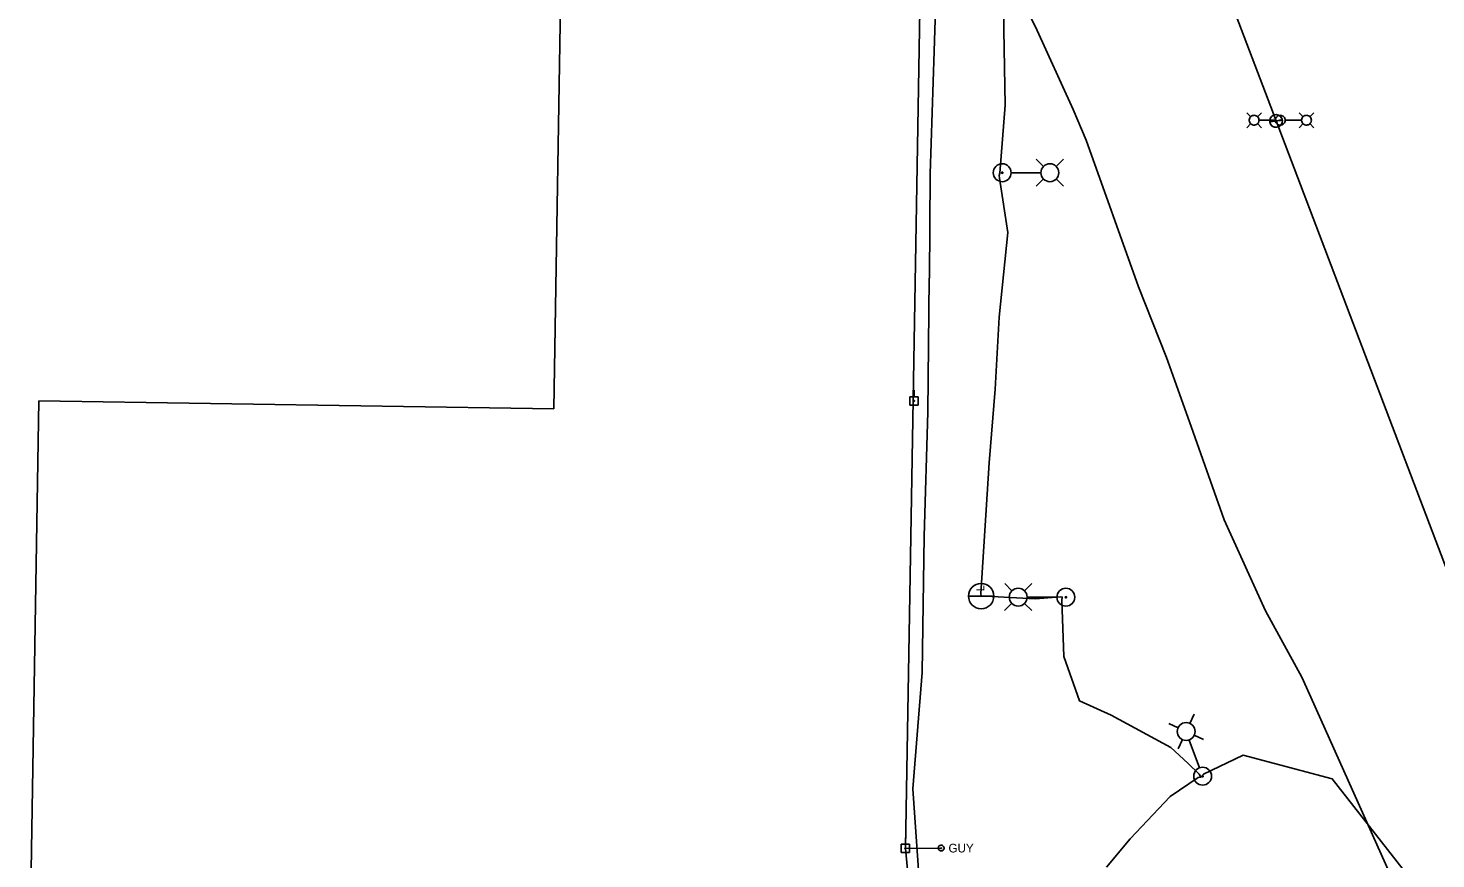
# Model space of a CAD drawing. Extents: x 596028 to 606371, y 330010 to 403088.
# Drawn here: x 603062 to 603685, y 350437 to 350805 of the extents above; entities that cross this region are included whole.
import ezdxf

# ---------------------------------------------------------------- set-up
doc = ezdxf.new("R2010")
doc.units = 0
for name, color, linetype in [('E_FTMS_Conduit', 7, 'Continuous'), ('E_LTG', 7, 'Continuous'), ('E_LTG_CID', 7, 'Continuous'), ('E_UTL_E_UG', 7, 'Continuous'), ('E_UTL_EGuyWire', 7, 'Continuous'), ('E_UTL_EPowerPole', 7, 'Continuous'), ('E_UTL_FO_UG_QWEST', 7, 'Continuous'), ('E_UTL_Overhead', 7, 'Continuous')]:
    doc.layers.add(name, color=color, linetype=linetype)

# ---------------------------------------------------------------- blocks, each defined once
blk = doc.blocks.new('_U288')
at = {"layer": 'E_LTG'}
blk.add_lwpolyline([(0.001, -0.171), (0.001, 0.172)], dxfattribs=at)
blk.add_circle((0.001, 0), 0.171, dxfattribs=at)
blk.add_arc((0.001, 0), 0.171, 90, 270, dxfattribs=at)
blk.add_text('L', height=0.108, dxfattribs=at).set_placement((0.066, -0.042))
blk = doc.blocks.new('_U272')
at = {"layer": 'E_LTG'}
blk.add_lwpolyline([(0.001, -0.171), (0.001, 0.172)], dxfattribs=at)
blk.add_circle((0.001, 0), 0.171, dxfattribs=at)
blk.add_arc((0.001, 0), 0.171, 90, 270, dxfattribs=at)
blk.add_text('L', height=0.108, dxfattribs=at).set_placement((0.066, -0.042))

msp = doc.modelspace()

# ---------------------------------------------------------------- linework, layer by layer
at = {"layer": 'E_FTMS_Conduit'}
msp.add_lwpolyline([(603683.28, 350388.39), (603627.38, 350513.3), (603625.35, 350517.8), (603609.26, 350547.29), (603590.93, 350587.57), (603576.33, 350628.92), (603565.39, 350659.37), (603552.92, 350690.81), (603529.87, 350755.72), (603524.01, 350769.33), (603507.4, 350805.93), (603488.24, 350844.06), (603483.2, 350870.26), (603473.58, 350908.61), (603465.8, 350950.07), (603458.47, 350983.69), (603437.61, 351034.41), (603419.58, 351080.05), (603403.21, 351158.05), (603376.31, 351235.86)], dxfattribs=at)
at = {"layer": 'E_LTG'}
for points in [[(603602.64, 350766.07), (603600.87, 350767.84)], [(603606.34, 350764.54), (603606.31, 350764.96), (603606.19, 350765.35), (603606, 350765.72), (603605.74, 350766.05), (603605.43, 350766.32), (603605.07, 350766.52), (603604.68, 350766.66), (603604.27, 350766.72), (603603.86, 350766.7), (603603.46, 350766.6), (603603.08, 350766.43), (603602.74, 350766.19), (603602.46, 350765.89), (603602.24, 350765.54), (603602.08, 350765.16), (603602, 350764.75), (603602, 350764.34), (603602.08, 350763.93), (603602.24, 350763.55), (603602.46, 350763.2), (603602.74, 350762.9), (603603.08, 350762.66), (603603.46, 350762.49), (603603.86, 350762.39), (603604.27, 350762.37), (603604.68, 350762.43), (603605.07, 350762.56), (603605.43, 350762.77), (603605.74, 350763.04), (603606, 350763.37), (603606.19, 350763.74), (603606.31, 350764.13), (603606.34, 350764.54)], [(603605.69, 350766.07), (603607.47, 350767.84)], [(603617.91, 350764.54), (603617.87, 350764.96), (603617.75, 350765.35), (603617.56, 350765.72), (603617.31, 350766.04), (603617, 350766.32), (603616.64, 350766.52), (603616.25, 350766.66), (603615.84, 350766.72), (603615.43, 350766.7), (603615.02, 350766.6), (603614.65, 350766.43), (603614.31, 350766.19), (603614.02, 350765.89), (603613.8, 350765.54), (603613.65, 350765.16), (603613.57, 350764.75), (603613.57, 350764.34), (603613.65, 350763.93), (603613.8, 350763.55), (603614.02, 350763.2), (603614.31, 350762.9), (603614.65, 350762.66), (603615.02, 350762.49), (603615.43, 350762.39), (603615.84, 350762.37), (603616.25, 350762.43), (603616.64, 350762.56), (603617, 350762.77), (603617.31, 350763.04), (603617.56, 350763.37), (603617.75, 350763.73), (603617.87, 350764.13), (603617.91, 350764.54)], [(603625.82, 350766.07), (603624.04, 350767.84)], [(603629.51, 350764.54), (603629.47, 350764.96), (603629.36, 350765.35), (603629.17, 350765.72), (603628.91, 350766.04), (603628.6, 350766.32), (603628.24, 350766.52), (603627.85, 350766.66), (603627.44, 350766.72), (603627.03, 350766.7), (603626.63, 350766.6), (603626.25, 350766.43), (603625.91, 350766.19), (603625.63, 350765.89), (603625.4, 350765.54), (603625.25, 350765.16), (603625.17, 350764.75), (603625.17, 350764.34), (603625.25, 350763.93), (603625.4, 350763.55), (603625.63, 350763.2), (603625.91, 350762.9), (603626.25, 350762.66), (603626.63, 350762.49), (603627.03, 350762.39), (603627.44, 350762.37), (603627.85, 350762.43), (603628.24, 350762.56), (603628.6, 350762.77), (603628.91, 350763.04), (603629.17, 350763.37), (603629.36, 350763.73), (603629.47, 350764.13), (603629.51, 350764.54)], [(603628.86, 350766.07), (603630.64, 350767.84)], [(603602.64, 350763.02), (603600.87, 350761.24)], [(603605.69, 350763.02), (603607.47, 350761.24)], [(603606.38, 350764.54), (603613.56, 350764.54)], [(603615.9, 350764.54), (603615.9, 350764.57), (603615.89, 350764.61), (603615.87, 350764.63), (603615.86, 350764.66), (603615.83, 350764.68), (603615.8, 350764.69), (603615.77, 350764.71), (603615.74, 350764.71), (603615.71, 350764.71), (603615.68, 350764.7), (603615.65, 350764.69), (603615.63, 350764.67), (603615.6, 350764.65), (603615.59, 350764.62), (603615.58, 350764.59), (603615.57, 350764.56), (603615.57, 350764.53), (603615.58, 350764.5), (603615.59, 350764.47), (603615.6, 350764.44), (603615.63, 350764.42), (603615.65, 350764.4), (603615.68, 350764.39), (603615.71, 350764.38), (603615.74, 350764.38), (603615.77, 350764.38), (603615.8, 350764.39), (603615.83, 350764.41), (603615.86, 350764.43), (603615.87, 350764.45), (603615.89, 350764.48), (603615.9, 350764.51), (603615.9, 350764.54)], [(603625.13, 350764.54), (603617.95, 350764.54)], [(603625.82, 350763.02), (603624.04, 350761.24)], [(603628.86, 350763.02), (603630.64, 350761.24)], [(603511, 350744.06), (603507.77, 350747.28)], [(603516.54, 350744.06), (603519.77, 350747.28)], [(603509.74, 350741.28), (603496.69, 350741.28)], [(603511, 350738.51), (603507.77, 350735.28)], [(603516.54, 350738.51), (603519.77, 350735.28)], [(603497, 350556.09), (603493.78, 350559.33)], [(603502.54, 350556.07), (603505.78, 350559.3)], [(603496.98, 350550.55), (603493.75, 350547.33)], [(603502.52, 350550.53), (603505.75, 350547.3)], [(603503.79, 350553.3), (603516.84, 350553.27)], [(603575.7, 350497.33), (603577.61, 350501.48)], [(603570.5, 350495.41), (603566.36, 350497.32)], [(603577.62, 350492.13), (603581.77, 350490.22)], [(603572.42, 350490.21), (603570.52, 350486.06)], [(603575.46, 350489.99), (603579.99, 350477.75)]]:
    msp.add_lwpolyline(points, dxfattribs=at)
for centre, radius in [((603492.67, 350741.28), 3.96), ((603492.67, 350741.28), 0.303), ((603513.77, 350741.28), 3.96), ((603499.76, 350553.31), 3.96), ((603520.86, 350553.26), 3.96), ((603520.86, 350553.26), 0.303), ((603574.07, 350493.77), 3.96), ((603581.38, 350473.98), 3.96), ((603581.38, 350473.98), 0.303)]:
    msp.add_circle(centre, radius, dxfattribs=at)
at = {"layer": 'E_LTG_CID'}
for points in [[(604318.05, 348339.7), (604287.36, 348606.91), (604242.16, 348872.6), (604188.57, 349120.13), (604125.01, 349362.84), (604050.82, 349602.08), (604014.23, 349708.06), (603966.43, 349837.54), (603869.82, 350091.09), (603838.85, 350172.22), (603784.41, 350315.72), (603699.29, 350539.43), (603613.87, 350764.2), (603510.34, 351036.54), (603442.84, 351213.06), (603357.76, 351436.96)], [(603580.58, 350473.53), (603579.82, 350474.91), (603574.76, 350479.76), (603567.26, 350486.74), (603540.84, 350501.01), (603526.89, 350507.31), (603519.96, 350527.04), (603519.11, 350552.01), (603519.26, 350553.28), (603518.57, 350553.45), (603507.25, 350552.53), (603488.13, 350553.6), (603484.67, 350553.73), (603483.36, 350553.72), (603483.27, 350554.85), (603484.6, 350575.79), (603486.87, 350612.75), (603489.62, 350645.46), (603491.33, 350677.37), (603495.09, 350714.78), (603491.49, 350738.84), (603491.38, 350740.03), (603491.57, 350741.16), (603494.03, 350771.18), (603493.35, 350804.53), (603492.94, 350842.91)], [(603613.87, 350764.2), (603615.73, 350764.54)], [(603538.88, 350433.66), (603549.37, 350446.22), (603567.07, 350464.96), (603579.39, 350473.35), (603580.58, 350473.53), (603581.78, 350474.86), (603599.32, 350483.29), (603638.74, 350472.78), (603670.13, 350432.71)]]:
    msp.add_lwpolyline(points, dxfattribs=at)
at = {"layer": 'E_UTL_E_UG'}
msp.add_line((603061.58, 350355.6), (603066.26, 350640.24), dxfattribs=at)
msp.add_lwpolyline([(603066.26, 350640.24), (603294.23, 350636.71), (603301.03, 351049.72)], dxfattribs=at)
at = {"layer": 'E_UTL_EGuyWire'}
msp.add_line((603465.68, 350442.13), (603449.86, 350441.98), dxfattribs=at)
for points in [[(603466.96, 350442.13), (603466.94, 350442.37), (603466.87, 350442.61), (603466.76, 350442.82), (603466.61, 350443.01), (603466.42, 350443.17), (603466.21, 350443.3), (603465.98, 350443.38), (603465.74, 350443.41), (603465.5, 350443.4), (603465.26, 350443.34), (603465.04, 350443.24), (603464.84, 350443.1), (603464.67, 350442.92), (603464.54, 350442.72), (603464.45, 350442.49), (603464.4, 350442.25), (603464.4, 350442.01), (603464.45, 350441.77), (603464.54, 350441.54), (603464.67, 350441.34), (603464.84, 350441.16), (603465.04, 350441.02), (603465.26, 350440.92), (603465.5, 350440.86), (603465.74, 350440.85), (603465.98, 350440.88), (603466.21, 350440.96), (603466.42, 350441.08), (603466.61, 350441.24), (603466.76, 350441.44), (603466.87, 350441.65), (603466.94, 350441.89), (603466.96, 350442.13)], [(603465.84, 350442.13), (603465.84, 350442.16), (603465.83, 350442.19), (603465.81, 350442.22), (603465.79, 350442.24), (603465.77, 350442.26), (603465.74, 350442.27), (603465.72, 350442.28), (603465.69, 350442.29), (603465.66, 350442.29), (603465.63, 350442.28), (603465.6, 350442.27), (603465.57, 350442.25), (603465.55, 350442.23), (603465.54, 350442.2), (603465.52, 350442.17), (603465.52, 350442.14), (603465.52, 350442.11), (603465.52, 350442.08), (603465.54, 350442.06), (603465.55, 350442.03), (603465.57, 350442.01), (603465.6, 350441.99), (603465.63, 350441.98), (603465.66, 350441.97), (603465.69, 350441.97), (603465.72, 350441.97), (603465.74, 350441.98), (603465.77, 350442), (603465.79, 350442.02), (603465.81, 350442.04), (603465.83, 350442.07), (603465.84, 350442.1), (603465.84, 350442.13)]]:
    msp.add_lwpolyline(points, dxfattribs=at)
at = {"layer": 'E_UTL_EPowerPole'}
for points in [[(603455.48, 350642.06), (603451.8, 350642.06)], [(603451.8, 350642.06), (603451.8, 350638.37)], [(603453.64, 350642.06), (603453.64, 350644.97)], [(603455.48, 350638.37), (603455.48, 350642.06)], [(603451.8, 350638.37), (603455.48, 350638.37)], [(603453.91, 350640.22), (603453.91, 350640.27), (603453.89, 350640.31), (603453.87, 350640.35), (603453.85, 350640.38), (603453.81, 350640.41), (603453.77, 350640.44), (603453.73, 350640.45), (603453.68, 350640.46), (603453.64, 350640.46), (603453.6, 350640.45), (603453.55, 350640.43), (603453.52, 350640.4), (603453.49, 350640.37), (603453.46, 350640.33), (603453.44, 350640.29), (603453.44, 350640.24), (603453.44, 350640.2), (603453.44, 350640.15), (603453.46, 350640.11), (603453.49, 350640.07), (603453.52, 350640.04), (603453.55, 350640.01), (603453.6, 350639.99), (603453.64, 350639.98), (603453.68, 350639.98), (603453.73, 350639.99), (603453.77, 350640), (603453.81, 350640.03), (603453.85, 350640.06), (603453.87, 350640.09), (603453.89, 350640.13), (603453.91, 350640.17), (603453.91, 350640.22)], [(603451.68, 350443.83), (603447.99, 350443.83)], [(603447.99, 350443.83), (603447.99, 350440.14)], [(603450.1, 350441.98), (603450.1, 350442.03), (603450.09, 350442.07), (603450.07, 350442.11), (603450.04, 350442.15), (603450, 350442.18), (603449.96, 350442.2), (603449.92, 350442.22), (603449.88, 350442.22), (603449.83, 350442.22), (603449.79, 350442.21), (603449.75, 350442.19), (603449.71, 350442.17), (603449.68, 350442.13), (603449.65, 350442.09), (603449.64, 350442.05), (603449.63, 350442.01), (603449.63, 350441.96), (603449.64, 350441.92), (603449.65, 350441.88), (603449.68, 350441.84), (603449.71, 350441.8), (603449.75, 350441.78), (603449.79, 350441.76), (603449.83, 350441.75), (603449.88, 350441.75), (603449.92, 350441.75), (603449.96, 350441.77), (603450, 350441.79), (603450.04, 350441.82), (603450.07, 350441.86), (603450.09, 350441.9), (603450.1, 350441.94), (603450.1, 350441.98)], [(603449.83, 350443.83), (603449.83, 350446.74)], [(603451.68, 350440.14), (603451.68, 350443.83)], [(603447.99, 350440.14), (603451.68, 350440.14)]]:
    msp.add_lwpolyline(points, dxfattribs=at)
at = {"layer": 'E_UTL_FO_UG_QWEST'}
msp.add_lwpolyline([(603456.32, 350421.92), (603453.14, 350468.35), (603457.26, 350519.89), (603458.06, 350580.31), (603459.78, 350635.27), (603460.41, 350694.56), (603460.42, 350694.52), (603460.77, 350740.82), (603462.52, 350795.19), (603465.43, 350883.25), (603460.42, 350911.12), (603422.96, 351015.55), (603399.52, 351073.87), (603379.61, 351132.32), (603357.48, 351186)], dxfattribs=at)
at = {"layer": 'E_UTL_Overhead'}
msp.add_lwpolyline([(603468.46, 350246.59), (603449.86, 350441.98), (603456.5, 350830.83), (603431.88, 350974.54), (603298.9, 351326.49)], dxfattribs=at)

# ---------------------------------------------------------------- block references
at = {"layer": 'E_LTG_CID'}
for name, p, xscale, yscale, rotation in [('_U272', (603613.88, 350764.19), 16.404166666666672, 16.404166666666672, 97.82095686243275), ('_U288', (603483.36, 350553.72), 32.80833333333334, 32.80833333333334, 89.99999999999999)]:
    msp.add_blockref(name, p, dxfattribs=dict(at, xscale=xscale, yscale=yscale, rotation=rotation))

# ---------------------------------------------------------------- texts
at = {"layer": 'E_UTL_EGuyWire'}
msp.add_text('GUY', height=3.85, dxfattribs=at).set_placement((603468.89, 350440.2))

doc.saveas('drawing.dxf')
